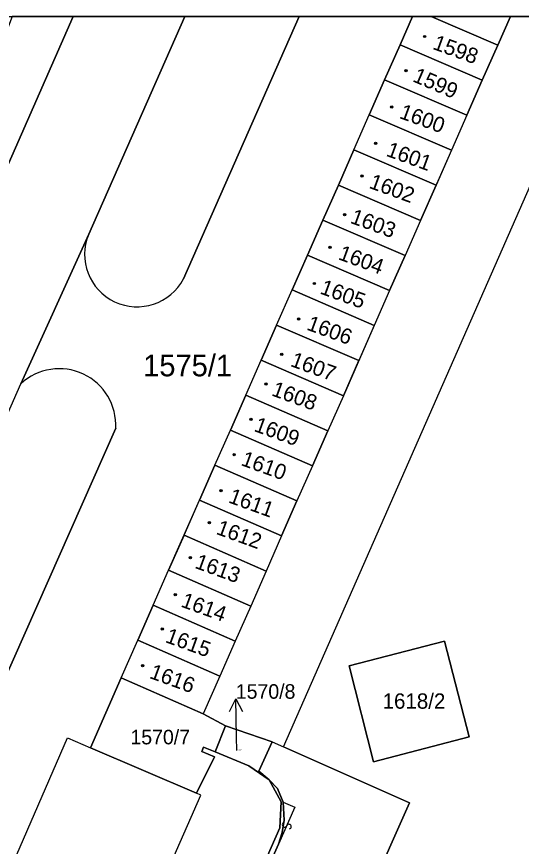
# Model space of a CAD drawing. Extents: x -596024 to -594475, y -1163820 to -1161957.
# Drawn here: x -595656.1 to -595616.6, y -1162021.9 to -1161956.9 of the extents above; entities that cross this region are included whole.
import ezdxf

# ---------------------------------------------------------------- set-up
doc = ezdxf.new("R2010")
doc.units = 0
for name, color, linetype in [('Level 1', 7, 'Continuous'), ('Level 13', 7, 'Continuous'), ('Level 3', 7, 'Continuous'), ('Level 4', 7, 'Continuous'), ('Level 5', 7, 'Continuous'), ('Level 57', 7, 'Continuous'), ('Level 60', 7, 'Continuous'), ('Vrstva 60', 7, 'Continuous'), ('Vrstva 63', 7, 'Continuous')]:
    doc.layers.add(name, color=color, linetype=linetype)

msp = doc.modelspace()

# ---------------------------------------------------------------- linework, layer by layer
at = {"layer": 'Level 1'}
for p, q in [((-595700.42, -1162067.92), (-595651.683, -1161956.88)), ((-595650.46, -1161973.92), (-595642.928, -1161956.88)), ((-595633.993, -1161956.88), (-595643.05, -1161977.42)), ((-595626.1, -1161959.1), (-595625.131, -1161956.88)), ((-595623.663, -1161956.88), (-595618.46, -1161959.11)), ((-595617.477, -1161956.88), (-595618.46, -1161959.11))]:
    msp.add_line(p, q, dxfattribs=at)
for points in [[(-595626.1, -1161959.1), (-595627.31, -1161961.84)], [(-595619.67, -1161961.85), (-595626.1, -1161959.1)], [(-595618.46, -1161959.11), (-595619.67, -1161961.85)], [(-595627.31, -1161961.84), (-595628.52, -1161964.58)], [(-595627.31, -1161961.84), (-595620.87, -1161964.6)], [(-595620.87, -1161964.6), (-595619.67, -1161961.85)], [(-595635.22, -1162014.07), (-595613.23, -1161964.03), (-595578.61, -1161979.26), (-595603.82, -1162038.28), (-595628.58, -1162025.68)], [(-595629.72, -1161967.32), (-595628.52, -1161964.58)], [(-595628.52, -1161964.58), (-595622.08, -1161967.34)], [(-595620.87, -1161964.6), (-595622.08, -1161967.34)], [(-595629.72, -1161967.32), (-595630.93, -1161970.07)], [(-595623.29, -1161970.09), (-595629.72, -1161967.32)], [(-595622.08, -1161967.34), (-595623.29, -1161970.09)], [(-595630.93, -1161970.07), (-595632.14, -1161972.81)], [(-595630.93, -1161970.07), (-595624.5, -1161972.84)], [(-595624.5, -1161972.84), (-595623.29, -1161970.09)], [(-595632.14, -1161972.81), (-595633.34, -1161975.55)], [(-595625.71, -1161975.58), (-595632.14, -1161972.81)], [(-595624.5, -1161972.84), (-595625.71, -1161975.58)], [(-595650.46, -1161973.92), (-595655.76, -1161985.63)], [(-595633.34, -1161975.55), (-595634.55, -1161978.29)], [(-595633.34, -1161975.55), (-595626.92, -1161978.33)], [(-595626.92, -1161978.33), (-595625.71, -1161975.58)], [(-595635.76, -1161981.04), (-595634.55, -1161978.29)], [(-595634.55, -1161978.29), (-595628.12, -1161981.07)], [(-595626.92, -1161978.33), (-595628.12, -1161981.07)], [(-595635.76, -1161981.04), (-595636.96, -1161983.78)], [(-595629.33, -1161983.82), (-595635.76, -1161981.04)], [(-595628.12, -1161981.07), (-595629.33, -1161983.82)], [(-595638.17, -1161986.52), (-595636.96, -1161983.78)], [(-595636.96, -1161983.78), (-595630.54, -1161986.57)], [(-595630.54, -1161986.57), (-595629.33, -1161983.82)], [(-595682.95, -1162047.47), (-595655.76, -1161985.63)], [(-595638.17, -1161986.52), (-595639.38, -1161989.26)], [(-595631.75, -1161989.31), (-595638.17, -1161986.52)], [(-595630.54, -1161986.57), (-595631.75, -1161989.31)], [(-595673.08, -1162044.96), (-595648.35, -1161989.12)], [(-595640.59, -1161992.01), (-595639.38, -1161989.26)], [(-595639.38, -1161989.26), (-595632.96, -1161992.06)], [(-595632.96, -1161992.06), (-595631.75, -1161989.31)], [(-595640.59, -1161992.01), (-595641.79, -1161994.75)], [(-595634.17, -1161994.8), (-595640.59, -1161992.01)], [(-595632.96, -1161992.06), (-595634.17, -1161994.8)], [(-595643, -1161997.49), (-595641.79, -1161994.75)], [(-595641.79, -1161994.75), (-595635.38, -1161997.55)], [(-595635.38, -1161997.55), (-595634.17, -1161994.8)], [(-595643, -1161997.49), (-595644.21, -1162000.23)], [(-595636.58, -1162000.3), (-595643, -1161997.49)], [(-595635.38, -1161997.55), (-595636.58, -1162000.3)], [(-595645.41, -1162002.97), (-595644.21, -1162000.23)], [(-595644.21, -1162000.23), (-595637.79, -1162003.04)], [(-595636.58, -1162000.3), (-595637.79, -1162003.04)], [(-595645.41, -1162002.97), (-595646.62, -1162005.72)], [(-595639, -1162005.79), (-595645.41, -1162002.97)], [(-595637.79, -1162003.04), (-595639, -1162005.79)], [(-595647.92, -1162008.67), (-595646.62, -1162005.72)], [(-595646.62, -1162005.72), (-595640.21, -1162008.53)], [(-595639, -1162005.79), (-595640.21, -1162008.53)], [(-595630.08, -1162007.73), (-595622.62, -1162005.79), (-595620.69, -1162013.29), (-595628.18, -1162015.23), (-595630.08, -1162007.73)], [(-595647.92, -1162008.67), (-595650.33, -1162014.14)], [(-595647.92, -1162008.67), (-595641.51, -1162011.49)], [(-595640.21, -1162008.53), (-595641.51, -1162011.49)], [(-595639.77, -1162012.42), (-595641.51, -1162011.49)], [(-595640.57, -1162014.45), (-595639.77, -1162012.42)], [(-595636.12, -1162013.67), (-595639.77, -1162012.42)], [(-595660.39, -1162034.78), (-595661.28, -1162034.4), (-595652.12, -1162013.37), (-595650.33, -1162014.14)], [(-595636.12, -1162013.67), (-595637.14, -1162015.96), (-595636.35, -1162016.66)], [(-595636.12, -1162013.67), (-595635.22, -1162014.07)], [(-595650.33, -1162014.14), (-595642.03, -1162017.7)], [(-595640.57, -1162014.45), (-595641.48, -1162014.08), (-595641.62, -1162014.42), (-595640.61, -1162014.84), (-595642.03, -1162017.7)], [(-595636.35, -1162016.66), (-595637.93, -1162015.54), (-595640.57, -1162014.45)], [(-595628.58, -1162025.68), (-595625.37, -1162018.45), (-595635.22, -1162014.07)], [(-595650.88, -1162038.8), (-595644.83, -1162041.54), (-595635.5, -1162020.4), (-595635.41, -1162018.38), (-595636.35, -1162016.66)], [(-595635.25, -1162018.39), (-595635.69, -1162017.33), (-595636.35, -1162016.66)], [(-595635.25, -1162018.39), (-595635.18, -1162019.82), (-595635.32, -1162020.77), (-595635.61, -1162021.68)], [(-595642.94, -1162038.19), (-595635.61, -1162021.68)]]:
    msp.add_lwpolyline(points, dxfattribs=at)
for centre, radius, start, end in [((-595646.677, -1161975.504), 4.102, 157.28442, 332.14959), ((-595652.758, -1161988.867), 4.415, 356.7119, 132.84862)]:
    msp.add_arc(centre, radius, start, end, dxfattribs=at)
at = {"layer": 'Level 13'}
for centre, start, end in [((-595635.138, -1162020.165), 103.19579, 335.78579), ((-595634.802, -1162020.316), 283.41024, 155.50824)]:
    msp.add_arc(centre, 0.184, start, end, dxfattribs=at)
at = {"layer": 'Level 3'}
for points in [[(-595650.88, -1162038.8), (-595641.7, -1162017.84), (-595642.03, -1162017.7)], [(-595635.25, -1162018.39), (-595634.33, -1162018.8), (-595635.61, -1162021.68)]]:
    msp.add_lwpolyline(points, dxfattribs=at)
at = {"layer": 'Level 5'}
for centre, radius in [((-595624.18, -1161958.44), 0.09), ((-595624.18, -1161958.44), 0.0521), ((-595625.63, -1161961.11), 0.09), ((-595625.63, -1161961.11), 0.0521), ((-595626.75, -1161963.95), 0.09), ((-595626.75, -1161963.95), 0.0521), ((-595628.02, -1161966.81), 0.09), ((-595628.02, -1161966.81), 0.0521), ((-595629.07, -1161969.36), 0.09), ((-595629.07, -1161969.36), 0.0521), ((-595630.44, -1161972.4), 0.09), ((-595630.44, -1161972.4), 0.0521), ((-595631.58, -1161974.96), 0.09), ((-595631.58, -1161974.96), 0.0521), ((-595632.81, -1161977.78), 0.09), ((-595632.81, -1161977.78), 0.0521), ((-595634.04, -1161980.57), 0.09), ((-595634.04, -1161980.57), 0.0521), ((-595635.36, -1161983.32), 0.09), ((-595635.36, -1161983.32), 0.0521), ((-595636.6, -1161985.65), 0.09), ((-595636.6, -1161985.65), 0.0521), ((-595637.77, -1161988.41), 0.09), ((-595637.77, -1161988.41), 0.0521), ((-595639.08, -1161991.18), 0.09), ((-595639.08, -1161991.18), 0.0521), ((-595640.11, -1161994), 0.09), ((-595640.11, -1161994), 0.0521), ((-595641.02, -1161996.51), 0.09), ((-595641.02, -1161996.51), 0.0521), ((-595642.5, -1161999.26), 0.09), ((-595642.5, -1161999.26), 0.0521), ((-595643.69, -1162002.16), 0.09), ((-595643.69, -1162002.16), 0.0521), ((-595644.71, -1162004.83), 0.09), ((-595644.71, -1162004.83), 0.0521), ((-595646.24, -1162007.7), 0.09), ((-595646.24, -1162007.7), 0.0521)]:
    msp.add_circle(centre, radius, dxfattribs=at)
at = {"layer": 'Level 57'}
for p, q in [((-595638.899, -1162013.3), (-595638.952, -1162010.3)), ((-595638.88, -1162014.35), (-595638.899, -1162013.3))]:
    msp.add_line(p, q, dxfattribs=at)
msp.add_lwpolyline([(-595639.434, -1162011.309), (-595638.952, -1162010.3), (-595638.434, -1162011.291)], dxfattribs=at)
at = {"layer": 'Level 60'}
for points in [[(-595626.1, -1161959.1), (-595619.67, -1161961.85), (-595620.87, -1161964.6), (-595627.31, -1161961.84)], [(-595627.31, -1161961.84), (-595620.87, -1161964.6), (-595622.08, -1161967.34), (-595628.52, -1161964.58)], [(-595578.61, -1161979.26), (-595603.82, -1162038.28), (-595628.58, -1162025.68), (-595625.37, -1162018.45), (-595635.22, -1162014.07), (-595613.23, -1161964.03)], [(-595622.08, -1161967.34), (-595623.29, -1161970.09), (-595629.72, -1161967.32), (-595628.52, -1161964.58)], [(-595629.72, -1161967.32), (-595623.29, -1161970.09), (-595624.5, -1161972.84), (-595630.93, -1161970.07)], [(-595630.93, -1161970.07), (-595624.5, -1161972.84), (-595625.71, -1161975.58), (-595632.14, -1161972.81)], [(-595632.14, -1161972.81), (-595625.71, -1161975.58), (-595626.92, -1161978.33), (-595633.34, -1161975.55)], [(-595633.34, -1161975.55), (-595626.92, -1161978.33), (-595628.12, -1161981.07), (-595634.55, -1161978.29)], [(-595634.55, -1161978.29), (-595628.12, -1161981.07), (-595629.33, -1161983.82), (-595635.76, -1161981.04)], [(-595635.76, -1161981.04), (-595629.33, -1161983.82), (-595630.54, -1161986.57), (-595636.96, -1161983.78)], [(-595636.96, -1161983.78), (-595630.54, -1161986.57), (-595631.75, -1161989.31), (-595638.17, -1161986.52)], [(-595638.17, -1161986.52), (-595631.75, -1161989.31), (-595632.96, -1161992.06), (-595639.38, -1161989.26)], [(-595639.38, -1161989.26), (-595632.96, -1161992.06), (-595634.17, -1161994.8), (-595640.59, -1161992.01)], [(-595640.59, -1161992.01), (-595634.17, -1161994.8), (-595635.38, -1161997.55), (-595641.79, -1161994.75)], [(-595641.79, -1161994.75), (-595635.38, -1161997.55), (-595636.58, -1162000.3), (-595643, -1161997.49)], [(-595643, -1161997.49), (-595636.58, -1162000.3), (-595637.79, -1162003.04), (-595644.21, -1162000.23)], [(-595644.21, -1162000.23), (-595637.79, -1162003.04), (-595639, -1162005.79), (-595645.41, -1162002.97)], [(-595645.41, -1162002.97), (-595639, -1162005.79), (-595640.21, -1162008.53), (-595646.62, -1162005.72)], [(-595646.62, -1162005.72), (-595640.21, -1162008.53), (-595641.51, -1162011.49), (-595647.92, -1162008.67)], [(-595622.62, -1162005.79), (-595630.08, -1162007.73), (-595628.18, -1162015.23), (-595620.69, -1162013.29)], [(-595630.08, -1162007.73), (-595622.62, -1162005.79), (-595620.69, -1162013.29), (-595628.18, -1162015.23)], [(-595641.51, -1162011.49), (-595639.77, -1162012.42), (-595640.57, -1162014.45), (-595641.48, -1162014.08), (-595641.62, -1162014.42), (-595640.61, -1162014.84), (-595642.03, -1162017.7), (-595650.33, -1162014.14), (-595647.92, -1162008.67)], [(-595636.35, -1162016.66), (-595637.93, -1162015.54), (-595640.57, -1162014.45), (-595639.77, -1162012.42), (-595636.12, -1162013.67), (-595637.14, -1162015.96)], [(-595661.28, -1162034.4), (-595652.12, -1162013.37), (-595650.33, -1162014.14), (-595642.03, -1162017.7), (-595640.61, -1162014.84), (-595641.62, -1162014.42), (-595641.48, -1162014.08), (-595640.57, -1162014.45), (-595637.93, -1162015.54), (-595636.35, -1162016.66), (-595635.41, -1162018.38), (-595635.5, -1162020.4), (-595644.83, -1162041.54), (-595650.88, -1162038.8), (-595660.39, -1162034.78)], [(-595635.58, -1162041.44), (-595642.94, -1162038.19), (-595635.61, -1162021.68), (-595635.32, -1162020.77), (-595635.18, -1162019.82), (-595635.25, -1162018.39), (-595635.69, -1162017.33), (-595636.35, -1162016.66), (-595637.14, -1162015.96), (-595636.12, -1162013.67), (-595635.22, -1162014.07), (-595625.37, -1162018.45), (-595628.58, -1162025.68)], [(-595635.25, -1162018.39), (-595635.18, -1162019.82), (-595635.32, -1162020.77), (-595635.61, -1162021.68), (-595642.94, -1162038.19), (-595643.96, -1162040.61), (-595646.62, -1162046.56), (-595648.38, -1162045.78), (-595653.01, -1162043.65), (-595650.88, -1162038.8), (-595644.83, -1162041.54), (-595635.5, -1162020.4), (-595635.41, -1162018.38), (-595636.35, -1162016.66), (-595635.69, -1162017.33)]]:
    msp.add_lwpolyline(points, close=True, dxfattribs=at)
for points in [[(-595682.95, -1162047.47), (-595655.76, -1161985.63)], [(-595648.35, -1161989.12), (-595673.08, -1162044.96), (-595675.04, -1162049.39), (-595675.7, -1162050.89)]]:
    msp.add_lwpolyline(points, dxfattribs=at)
msp.add_arc((-595652.758, -1161988.867), 4.415, 356.71189, 132.84862, dxfattribs=at)
at = {"layer": 'Vrstva 60'}
msp.add_line((-595650.46, -1161973.92), (-595655.76, -1161985.63), dxfattribs=at)
for points in [[(-595642.928, -1161956.88), (-595651.683, -1161956.88), (-595700.42, -1162067.92), (-595714.28, -1162100.65), (-595763.48, -1162212.38), (-595762.1, -1162212.98), (-595755.16, -1162216.01), (-595739.48, -1162180.64), (-595719.28, -1162134.23), (-595717.11, -1162129.24), (-595707.38, -1162106.85), (-595708.77, -1162106.24), (-595707.38, -1162103.08), (-595698.23, -1162081.48), (-595688.29, -1162059.74), (-595682.95, -1162047.47), (-595655.76, -1161985.63), (-595650.46, -1161973.92)], [(-595623.663, -1161956.88), (-595625.131, -1161956.88), (-595626.1, -1161959.1), (-595619.67, -1161961.85), (-595618.46, -1161959.11)], [(-595617.477, -1161956.88), (-595623.663, -1161956.88), (-595618.46, -1161959.11)]]:
    msp.add_lwpolyline(points, close=True, dxfattribs=at)
for points in [[(-595700.42, -1162067.92), (-595651.683, -1161956.88), (-595656.438, -1161956.88), (-595660.93, -1161968.65), (-595660.82, -1161968.69), (-595660.93, -1161968.99), (-595661.27, -1161968.87), (-595661.23, -1161968.75), (-595663.18, -1161968.04), (-595663.3, -1161968.36), (-595663.41, -1161968.31), (-595669.72, -1161984.93), (-595676.15, -1162001.88), (-595682.49, -1162018.59), (-595682.38, -1162018.63), (-595682.49, -1162018.93), (-595682.83, -1162018.81), (-595682.79, -1162018.7), (-595684.7, -1162018.03), (-595684.82, -1162018.35), (-595684.93, -1162018.31), (-595691.18, -1162035.02), (-595697.57, -1162052.09)], [(-595661.28, -1162034.4), (-595652.12, -1162013.37), (-595650.33, -1162014.14), (-595647.92, -1162008.67), (-595646.62, -1162005.72), (-595645.41, -1162002.97), (-595644.21, -1162000.23), (-595641.79, -1161994.75), (-595640.59, -1161992.01), (-595639.38, -1161989.26), (-595636.96, -1161983.78), (-595635.76, -1161981.04), (-595634.55, -1161978.29), (-595633.34, -1161975.55), (-595632.14, -1161972.81), (-595630.93, -1161970.07), (-595629.72, -1161967.32), (-595628.52, -1161964.58), (-595626.1, -1161959.1), (-595625.131, -1161956.88), (-595633.993, -1161956.88), (-595643.05, -1161977.42)], [(-595643.05, -1161977.42), (-595633.993, -1161956.88), (-595642.928, -1161956.88), (-595650.46, -1161973.92)], [(-595614.971, -1161956.88), (-595617.477, -1161956.88), (-595618.46, -1161959.11), (-595619.67, -1161961.85), (-595620.87, -1161964.6), (-595622.08, -1161967.34), (-595624.5, -1161972.84), (-595625.71, -1161975.58), (-595626.92, -1161978.33), (-595628.12, -1161981.07), (-595630.54, -1161986.57), (-595631.75, -1161989.31), (-595632.96, -1161992.06), (-595634.17, -1161994.8), (-595635.38, -1161997.55), (-595636.58, -1162000.3), (-595637.79, -1162003.04), (-595639, -1162005.79), (-595640.21, -1162008.53), (-595641.51, -1162011.49), (-595639.77, -1162012.42), (-595636.12, -1162013.67), (-595635.22, -1162014.07), (-595613.23, -1161964.03)], [(-595648.35, -1161989.12), (-595673.08, -1162044.96)]]:
    msp.add_lwpolyline(points, dxfattribs=at)
for centre, radius, start, end in [((-595646.677, -1161975.504), 4.102, 157.28442, 332.14959), ((-595646.677, -1161975.504), 4.102, 157.28442, 332.14959), ((-595652.758, -1161988.867), 4.415, 356.7119, 132.84862)]:
    msp.add_arc(centre, radius, start, end, dxfattribs=at)
at = {"layer": 'Vrstva 63'}
msp.add_lwpolyline([(-594475.47, -1163820.23), (-596024.42, -1163820.23), (-596024.42, -1161956.88), (-594475.47, -1161956.88)], close=True, dxfattribs=at)

# ---------------------------------------------------------------- texts
at = {"layer": 'Level 4'}
for s, rotation, p in [('1598', 340.00002, (-595623.62, -1161959.4)), ('1599', 336.72105, (-595625.19, -1161961.93)), ('1600', 340.00002, (-595626.23, -1161964.81)), ('1601', 340.00002, (-595627.26, -1161967.77)), ('1602', 340.00002, (-595628.6, -1161970.28)), ('1603', 340.00002, (-595630.07, -1161973.02)), ('1604', 340.00002, (-595631.01, -1161975.87)), ('1605', 340.00002, (-595632.44, -1161978.55)), ('1606', 340.00002, (-595633.48, -1161981.38)), ('1607', 340.00002, (-595634.75, -1161984.23)), ('1608', 340.00002, (-595636.23, -1161986.53)), ('1609', 340.00002, (-595637.6, -1161989.32)), ('1610', 340.00002, (-595638.62, -1161991.99)), ('1611', 340.00002, (-595639.6, -1161994.91)), ('1612', 340.00002, (-595640.56, -1161997.38)), ('1613', 340.00002, (-595642.23, -1162000.04)), ('1614', 340.00002, (-595643.32, -1162003.07)), ('1615', 340.00002, (-595644.54, -1162005.85)), ('1616', 340.00002, (-595645.78, -1162008.66))]:
    msp.add_text(s, height=1.2, rotation=rotation, dxfattribs=at).set_placement(p)
for s, height, p in [('1575/1', 1.7, (-595646.2, -1161985.05)), ('1618/2', 1.2, (-595627.469, -1162011.08)), ('1570/7', 1.14, (-595647.196, -1162013.87)), ('1570/8', 0.1, (-595638.88, -1162014.35))]:
    msp.add_text(s, height=height, dxfattribs=at).set_placement(p)
at = {"layer": 'Level 57'}
msp.add_text('1570/8', height=1.14, dxfattribs=at).set_placement((-595638.952, -1162010.3))

doc.saveas('drawing.dxf')
